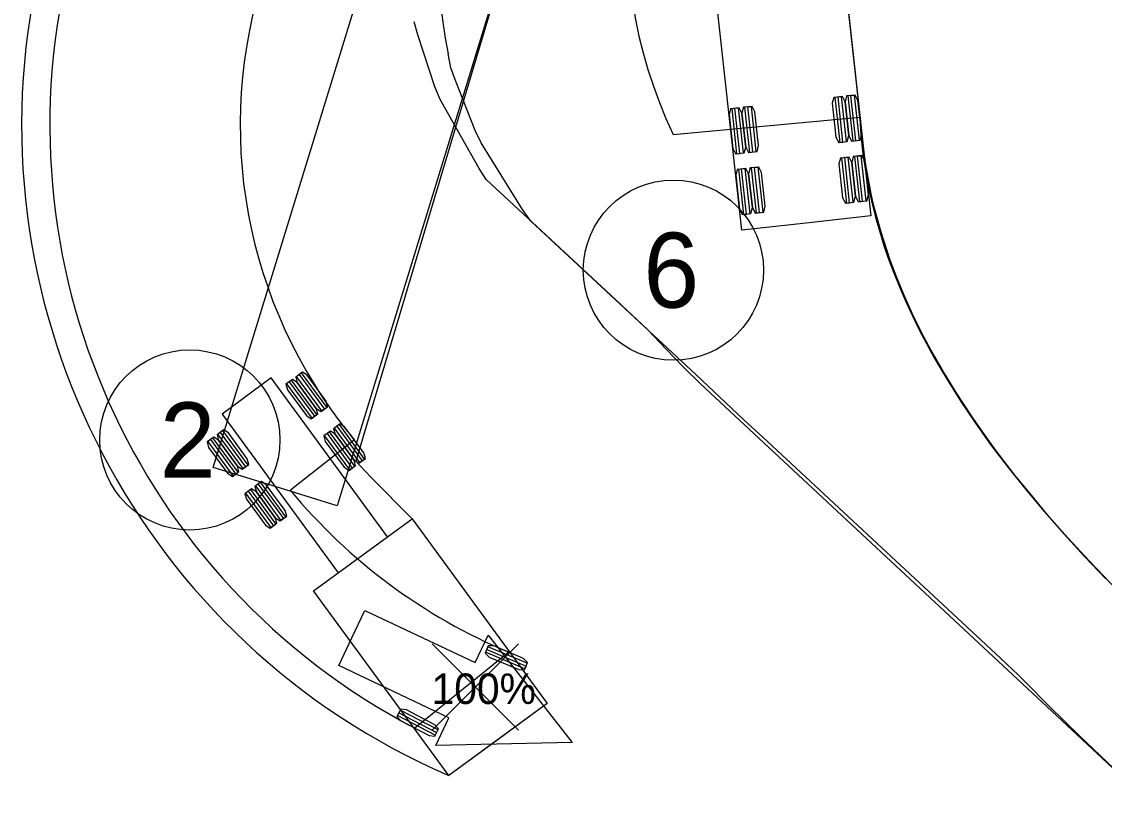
# Model space of a CAD drawing. Extents: x 1475900 to 1484331, y 375914 to 383395.
# Drawn here: x 1478701.4 to 1478772.4, y 379888.8 to 379939.6 of the extents above; entities that cross this region are included whole.
import ezdxf

# ---------------------------------------------------------------- set-up
doc = ezdxf.new("R2010")
doc.units = 0
doc.layers.add('PM_X_Misc', color=7, linetype='Continuous')
doc.layers.add('PM_X_Misc (Construction)', color=7, linetype='Continuous')

# ---------------------------------------------------------------- blocks, each defined once
blk = doc.blocks.new('ATRPTH_1')
at = {"layer": 'PM_X_Misc'}
for p, q in [((375835.381, 96491.944), (375835.466, 96491.805)), ((375836.049, 96491.018), (375834.981, 96490.181)), ((375838.617, 96487.485), (375837.055, 96486.221))]:
    blk.add_line(p, q, dxfattribs=at)
for points in [[(375839.032, 96500.576), (375836.07, 96490.664), (375836.32, 96490.396), (375837.009, 96489.706), (375839.26, 96486.632), (375837.62, 96485.432)], [(375833.695, 96490.558), (375837.275, 96502.213), (375838.306, 96501.896), (375839.338, 96501.579), (375835.759, 96489.924), (375834.727, 96490.241), (375833.695, 96490.558), (375833.695, 96490.558)], [(375835.588, 96491.562), (375835.167, 96492.136), (375835.126, 96492.106), (375835.547, 96491.532), (375835.506, 96491.502), (375835.085, 96492.076), (375835.072, 96492.066), (375835.097, 96491.974), (375835.412, 96491.543), (375835.492, 96491.492), (375835.601, 96491.572), (375835.576, 96491.663), (375835.261, 96492.094), (375835.181, 96492.146), (375835.072, 96492.066)], [(375836.599, 96489.406), (375834.663, 96492.05), (375833.844, 96491.45), (375835.779, 96488.806), (375836.599, 96489.406)], [(375835.424, 96491.442), (375835.003, 96492.016), (375834.962, 96491.985), (375835.383, 96491.412), (375835.342, 96491.382), (375834.921, 96491.955), (375834.908, 96491.945), (375834.933, 96491.854), (375835.248, 96491.423), (375835.328, 96491.372), (375835.437, 96491.452), (375835.412, 96491.543), (375835.097, 96491.974), (375835.017, 96492.026), (375834.908, 96491.945)], [(375834.276, 96490.601), (375833.856, 96491.175), (375833.815, 96491.145), (375834.235, 96490.571), (375834.194, 96490.541), (375833.774, 96491.115), (375833.76, 96491.105), (375833.785, 96491.013), (375834.1, 96490.583), (375834.18, 96490.531), (375834.29, 96490.611), (375834.264, 96490.703), (375833.949, 96491.134), (375833.869, 96491.185), (375833.76, 96491.105)], [(375836.054, 96490.581), (375835.634, 96491.155), (375835.593, 96491.125), (375836.013, 96490.551), (375835.972, 96490.521), (375835.552, 96491.095), (375835.538, 96491.085), (375835.563, 96490.993), (375835.878, 96490.563), (375835.958, 96490.511), (375836.067, 96490.591), (375836.042, 96490.683), (375835.727, 96491.113), (375835.647, 96491.165), (375835.538, 96491.085)], [(375836.218, 96490.701), (375835.798, 96491.275), (375835.757, 96491.245), (375836.177, 96490.671), (375836.136, 96490.641), (375835.716, 96491.215), (375835.702, 96491.205), (375835.727, 96491.113), (375836.042, 96490.683), (375836.122, 96490.631), (375836.231, 96490.711), (375836.206, 96490.803), (375835.891, 96491.233), (375835.811, 96491.285), (375835.702, 96491.205)], [(375834.112, 96490.481), (375833.692, 96491.055), (375833.651, 96491.025), (375834.071, 96490.451), (375834.03, 96490.421), (375833.61, 96490.995), (375833.596, 96490.985), (375833.621, 96490.893), (375833.936, 96490.463), (375834.016, 96490.411), (375834.126, 96490.491), (375834.1, 96490.583), (375833.785, 96491.013), (375833.705, 96491.065), (375833.596, 96490.985)], [(375834.906, 96489.741), (375834.486, 96490.314), (375834.445, 96490.284), (375834.865, 96489.711), (375834.824, 96489.681), (375834.404, 96490.254), (375834.39, 96490.244), (375834.415, 96490.153), (375834.731, 96489.722), (375834.81, 96489.671), (375834.92, 96489.751), (375834.895, 96489.842), (375834.579, 96490.273), (375834.5, 96490.324), (375834.39, 96490.244)], [(375834.742, 96489.621), (375834.322, 96490.194), (375834.281, 96490.164), (375834.701, 96489.591), (375834.66, 96489.561), (375834.24, 96490.134), (375834.226, 96490.124), (375834.252, 96490.033), (375834.567, 96489.602), (375834.646, 96489.551), (375834.756, 96489.631), (375834.731, 96489.722), (375834.415, 96490.153), (375834.336, 96490.204), (375834.226, 96490.124)], [(375837.62, 96485.432), (375835.369, 96488.506), (375837.009, 96489.706), (375839.26, 96486.632), (375838.44, 96486.032), (375837.62, 96485.432), (375837.62, 96485.432)], [(375838.925, 96487.301), (375838.269, 96487.576), (375838.25, 96487.53), (375838.905, 96487.254), (375838.886, 96487.207), (375838.23, 96487.483), (375838.223, 96487.467), (375838.292, 96487.401), (375838.784, 96487.195), (375838.879, 96487.192), (375838.932, 96487.316), (375838.863, 96487.382), (375838.371, 96487.589), (375838.276, 96487.592), (375838.223, 96487.467)], [(375837.44, 96486.192), (375836.81, 96486.521), (375836.787, 96486.476), (375837.417, 96486.147), (375837.393, 96486.102), (375836.763, 96486.431), (375836.755, 96486.416), (375836.818, 96486.345), (375837.291, 96486.098), (375837.386, 96486.087), (375837.448, 96486.207), (375837.385, 96486.278), (375836.913, 96486.525), (375836.818, 96486.536), (375836.755, 96486.416)]]:
    blk.add_lwpolyline(points, dxfattribs=at)
for radius, start, end in [(8.159, 154.6205, 211.9328), (11.328, 165.5904, 242.3887), (11.798, 168.6581, 246.6027), (8.162, 213.0785, 219.956), (9.518, 219.6904, 247.2003)]:
    blk.add_arc((375842.305, 96496.259), radius, start, end, dxfattribs=at)
at = {"layer": 'PM_X_Misc (Construction)'}
for p, q in [((375837.34, 96486.187), (375838.779, 96487.626)), ((375838.779, 96486.187), (375837.34, 96487.626))]:
    blk.add_line(p, q, dxfattribs=at)
blk.add_lwpolyline([(375836.004, 96487.723), (375836.222, 96488.182), (375838.057, 96487.311), (375838.275, 96487.769), (375839.675, 96485.98), (375837.404, 96485.934), (375837.622, 96486.393), (375835.786, 96487.264), (375836.004, 96487.723)], dxfattribs=at)
blk.add_circle((375833.307, 96491.018), 1.5, dxfattribs=at)
for s, height, p in [('2', 1.25, (375832.807, 96490.393)), ('100%', 0.508, (375837.332, 96486.623))]:
    blk.add_text(s, height=height, dxfattribs=at).set_placement(p)
blk = doc.blocks.new('ATRPTH_4')
at = {"layer": 'PM_X_Misc'}
for points in [[(375843.411, 96506.061), (375844.536, 96495.758), (375844.557, 96495.597), (375844.645, 96495.117), (375844.681, 96494.96), (375844.811, 96494.485), (375844.963, 96494.016), (375845.08, 96493.71), (375845.205, 96493.406), (375845.341, 96493.108), (375845.485, 96492.812), (375845.639, 96492.523), (375845.888, 96492.09), (375846.062, 96491.806), (375846.339, 96491.386), (375846.532, 96491.109), (375846.729, 96490.836), (375847.039, 96490.433), (375847.364, 96490.037), (375847.585, 96489.774), (375847.928, 96489.388), (375848.28, 96489.004), (375848.764, 96488.5)], [(375843.309, 96506.866), (375844.644, 96494.748), (375843.571, 96494.629), (375842.498, 96494.511), (375841.163, 96506.63), (375842.236, 96506.748), (375843.309, 96506.866), (375843.309, 96506.866)], [(375862.923, 96472.293), (375849.554, 96484.734), (375848.585, 96485.638), (375847.743, 96486.425), (375841.812, 96491.952), (375841.524, 96492.238), (375841.239, 96492.531), (375840.935, 96492.849), (375840.315, 96493.428), (375838.243, 96495.352), (375838.125, 96495.537), (375837.473, 96496.687), (375837.387, 96496.895), (375837.105, 96497.761), (375837.044, 96497.981)], [(375862.458, 96472.726), (375848.806, 96485.441), (375848.132, 96486.083), (375847.61, 96486.594), (375847.227, 96486.978), (375847.101, 96487.107), (375846.722, 96487.463), (375842.846, 96491.066), (375842.533, 96491.353), (375841.734, 96492.107), (375838.987, 96494.66), (375838.849, 96494.855), (375838.156, 96495.962), (375838.056, 96496.171), (375837.729, 96497), (375837.656, 96497.214), (375837.608, 96497.447)], [(375844.261, 96496.747), (375844.344, 96495.996), (375844.397, 96496.001), (375844.315, 96496.753), (375844.368, 96496.758), (375844.451, 96496.007), (375844.469, 96496.009), (375844.494, 96496.107), (375844.432, 96496.67), (375844.386, 96496.76), (375844.243, 96496.745), (375844.218, 96496.647), (375844.28, 96496.084), (375844.326, 96495.994), (375844.469, 96496.009)], [(375842.544, 96496.558), (375842.627, 96495.806), (375842.681, 96495.812), (375842.598, 96496.563), (375842.652, 96496.569), (375842.734, 96495.818), (375842.752, 96495.82), (375842.778, 96495.918), (375842.716, 96496.481), (375842.669, 96496.571), (375842.526, 96496.556), (375842.501, 96496.458), (375842.563, 96495.894), (375842.609, 96495.804), (375842.752, 96495.82)], [(375844.046, 96496.723), (375844.129, 96495.972), (375844.183, 96495.978), (375844.1, 96496.729), (375844.154, 96496.735), (375844.236, 96495.984), (375844.254, 96495.986), (375844.28, 96496.084), (375844.218, 96496.647), (375844.172, 96496.737), (375844.029, 96496.721), (375844.003, 96496.623), (375844.065, 96496.06), (375844.111, 96495.97), (375844.254, 96495.986)], [(375841.356, 96496.101), (375844.463, 96496.389), (375844.482, 96496.089), (375844.514, 96495.781), (375844.561, 96495.466), (375844.623, 96495.144), (375844.673, 96494.926), (375844.73, 96494.705), (375844.794, 96494.482), (375844.865, 96494.256), (375844.943, 96494.028), (375845.029, 96493.799), (375845.123, 96493.567), (375845.223, 96493.333), (375845.332, 96493.098), (375845.448, 96492.861), (375845.572, 96492.623), (375845.703, 96492.384), (375845.915, 96492.023), (375846.143, 96491.66), (375846.389, 96491.295), (375846.651, 96490.928), (375846.931, 96490.56), (375847.226, 96490.191), (375847.537, 96489.822), (375847.863, 96489.451), (375848.203, 96489.08), (375848.557, 96488.708)], [(375842.33, 96496.534), (375842.412, 96495.783), (375842.466, 96495.789), (375842.383, 96496.54), (375842.437, 96496.546), (375842.52, 96495.795), (375842.538, 96495.797), (375842.563, 96495.894), (375842.501, 96496.458), (375842.455, 96496.548), (375842.312, 96496.532), (375842.286, 96496.434), (375842.348, 96495.871), (375842.394, 96495.781), (375842.538, 96495.797)], [(375844.158, 96495.713), (375844.24, 96494.962), (375844.294, 96494.968), (375844.211, 96495.719), (375844.265, 96495.725), (375844.348, 96494.974), (375844.366, 96494.976), (375844.391, 96495.074), (375844.329, 96495.637), (375844.283, 96495.727), (375844.14, 96495.711), (375844.114, 96495.613), (375844.176, 96495.05), (375844.223, 96494.96), (375844.366, 96494.976)], [(375844.372, 96495.737), (375844.455, 96494.986), (375844.509, 96494.992), (375844.426, 96495.743), (375844.48, 96495.749), (375844.562, 96494.997), (375844.58, 96494.999), (375844.606, 96495.097), (375844.544, 96495.661), (375844.497, 96495.751), (375844.354, 96495.735), (375844.329, 96495.637), (375844.391, 96495.074), (375844.437, 96494.984), (375844.58, 96494.999)], [(375842.441, 96495.524), (375842.524, 96494.773), (375842.577, 96494.779), (375842.495, 96495.53), (375842.548, 96495.536), (375842.631, 96494.785), (375842.649, 96494.787), (375842.674, 96494.885), (375842.612, 96495.448), (375842.566, 96495.538), (375842.423, 96495.522), (375842.398, 96495.424), (375842.46, 96494.861), (375842.506, 96494.771), (375842.649, 96494.787)], [(375842.655, 96495.548), (375842.738, 96494.797), (375842.792, 96494.802), (375842.709, 96495.554), (375842.763, 96495.559), (375842.846, 96494.808), (375842.863, 96494.81), (375842.889, 96494.908), (375842.827, 96495.471), (375842.781, 96495.561), (375842.638, 96495.546), (375842.612, 96495.448), (375842.674, 96494.885), (375842.72, 96494.795), (375842.863, 96494.81)]]:
    blk.add_lwpolyline(points, dxfattribs=at)
for centre, radius, start, end in [((375848.732, 96499.589), 11.328, 108.369, 190.8985), ((375848.733, 96499.589), 8.16, 141.1217, 205.303)]:
    blk.add_arc(centre, radius, start, end, dxfattribs=at)
at = {"layer": 'PM_X_Misc (Construction)'}
blk.add_circle((375841.359, 96493.845), 1.5, dxfattribs=at)
blk.add_text('6', height=1.25, dxfattribs=at).set_placement((375840.859, 96493.22))

msp = doc.modelspace()

# ---------------------------------------------------------------- block references
at = {"layer": 'PM_X_Misc', "xscale": 3.937007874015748, "yscale": 3.937007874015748}
for name in ['ATRPTH_1', 'ATRPTH_4']:
    msp.add_blockref(name, (-946.236, 26.336), dxfattribs=at)

doc.saveas('drawing.dxf')
